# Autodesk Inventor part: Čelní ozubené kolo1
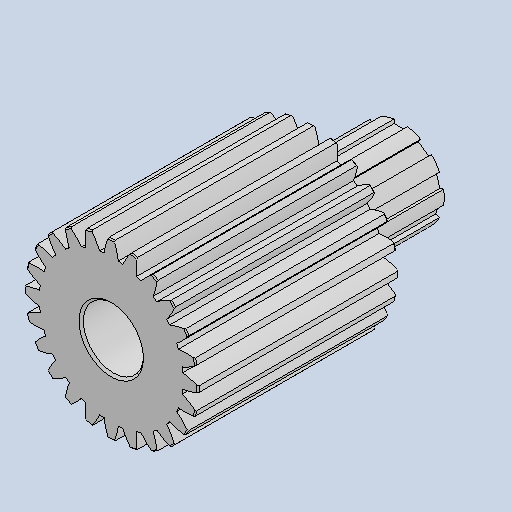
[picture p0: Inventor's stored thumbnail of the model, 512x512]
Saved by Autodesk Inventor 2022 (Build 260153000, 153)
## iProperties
CustomPartVersion: 1
Created: 2025-05
Part Number: Čelní ozubené kolo1
Material: Všeobecné
Document SubType Name: Modeling
Designer: jbart
Categories: <?xml version="1.0" encoding="UTF-16"?> <MemberInstance><Categories><FamilyTemplate><FamilyTemplateParameter ValueType="xs:double" Id="1" ObjectReferenceKey="da
Density: 1 g/cm^3
Appearance: Výchozí
Mass: 2650.81 g
Surface Area: 2605.11 cm^2
Volume: 2650.81 cm^3
Author: jbart
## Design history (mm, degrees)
sketch "Sketch1"
  geometry: C1 r 77.994 at (0, 0)
  constraints: 1 centre point
  dimensions: "d0" = 155.9887 diameter of C1 (= da_da)
extrude "Extrusion1" new body sketch "Sketch1" distance "d1" = 180 (= da_b); taper "d2" = 0 deg
workplane "Work Plane2"
sketch "Sketch2"
  geometry: C1 r 77.994 at (0, 0) reference; C2 r 72 at (0, 0)
  constraints: 1 centre point, 1 coincident
  dimensions: "d3" = 144 diameter of C2 (= da_d)
feature "Roztečný průměr" sketch "Sketch2" dims "d4" = 10, "d5" = 0
workplane "Work Plane8"
workplane "Work Plane9"
feature "Čelní ozubené kolo" dims "da_b" = 180, "da_d" = 144, "da_aw" = 252.61673, "da_da" = 155.9887, "da_df" = 129, "da_dw" = 144.35242, angle "da_beta" = 0 deg, "da_lefttooth" = 0, "da_righttooth" = 0
sketch "Náčrt3"
  geometry: C1 r 34 at (0, 0); 1 further point
  constraints: 1 centre point, 1 coincident
  dimensions: "d49" = 68 diameter of C1
extrude "Vysunutí2" join sketch "Náčrt3" distance "d50" = 10; taper "d51" = 0 deg
sketch "Náčrt4"
  geometry: C1 r 39 at (0, 0); 1 further point
  constraints: 1 centre point, 1 coincident
  dimensions: "d52" = 78 diameter of C1
extrude "Vysunutí3" join sketch "Náčrt4" distance "d53" = 70; taper "d54" = 0 deg
sketch "Náčrt5"
  geometry: L1 (-6, 38.536)-(-6, 35); L2 (-6, 35)-(6, 35); L3 (6, 35)-(6, 38.536); A1 r 39 centre (0, 0) between (-6, 38.536) and (6, 38.536) reference; 2 further points
  constraints: 6 end point, 2 perpendicular, 2 point on circle, 1 midpoint, 1 vertical, 1 vertical alignment
  dimensions: "d55" = 35 distance from line of L2 point (0, 0); "d56" = 12 distance of L1.end L2.end
extrude "Vysunutí4" cut sketch "Náčrt5" stored distance "d57" = 0; taper "d58" = 0 deg
pattern_circular "Kruhové pole1" dims angle "d60" = 360 deg
sketch "Náčrt6"
  geometry: C1 r 27 at (0, 0); 1 further point
  constraints: 1 centre point, 1 coincident
  dimensions: "d62" = 54 diameter of C1
extrude "Vysunutí5" cut sketch "Náčrt6" extent not by distance; stored distance "d63" = 0; taper "d64" = 0 deg
chamfer "Zkosení1" distance "d65" = 2; stored, may be unused: second distance "d66" = 2, angle "d67" = 45 deg
chamfer "Zkosení2" distance "d68" = 1; stored, may be unused: second distance "d69" = 2, angle "d70" = 45 deg
fillet "Zaoblení1" dims "d71" = 3
body "Solid1"
body "Srf1"
node "Promítnutá smyčka1"
other parameters: "d16" = 252.61673 (= da_aw), "d17" = 0, "d34" = 7.5 deg (computed from da_z), "d39" = 0, "d41" = 0, "d43" = 252.61673 (= da_aw), "d46" = 252.61673 (= da_aw), "d47" = 0, "d48" = 0
